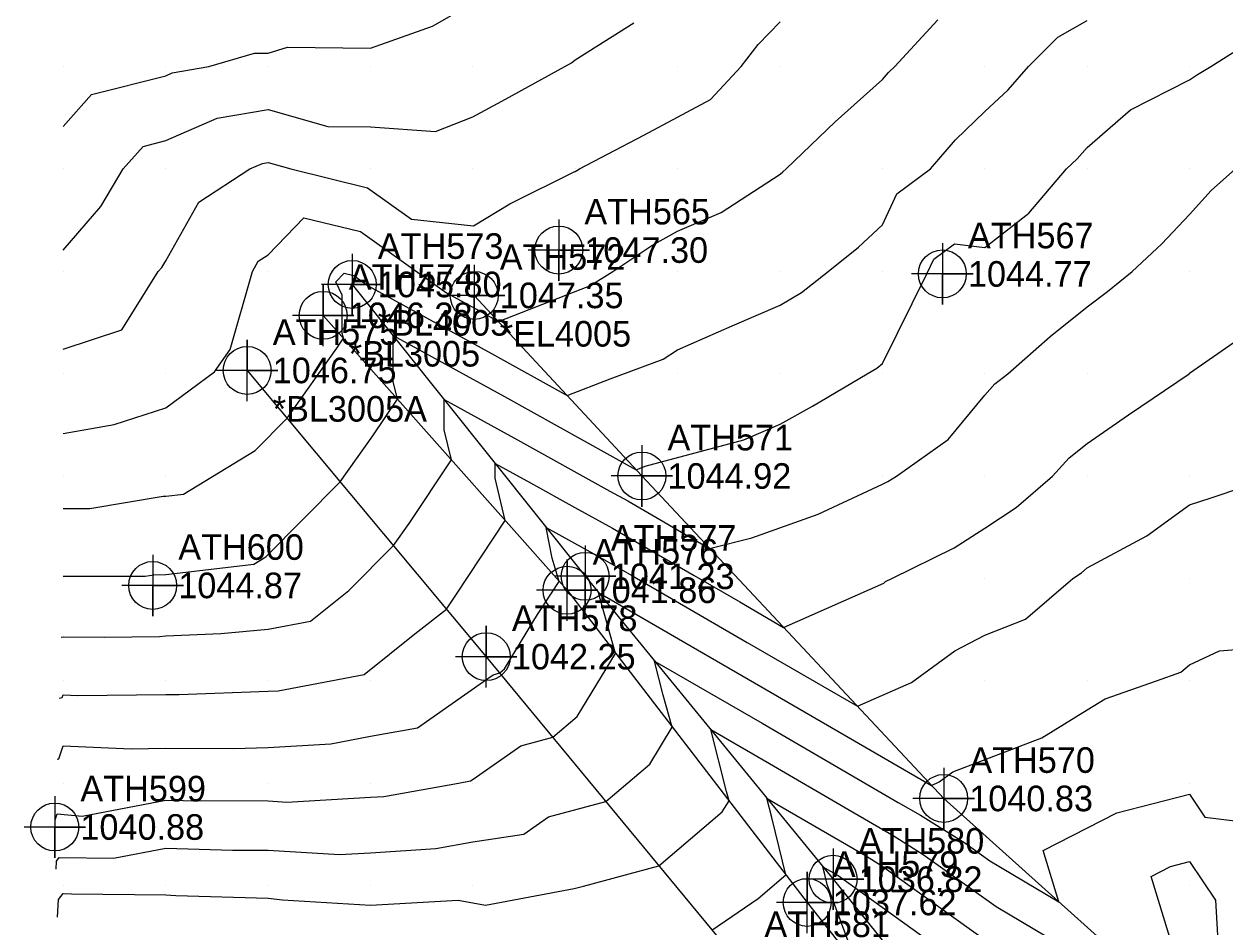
# Model space of a CAD drawing. Extents: x 1213164 to 1213550, y 766120 to 766870.
# Drawn here: x 1213226.2 to 1213343.5, y 766656 to 766744.2 of the extents above; entities that cross this region are included whole.
import ezdxf

# ---------------------------------------------------------------- set-up
doc = ezdxf.new("R2010")
doc.units = 0
for name, color, linetype in [('Default', 7, 'Continuous'), ('Exist DTM Breakline', 7, 'Continuous'), ('Exist DTM Breakline Cogo Comment', 7, 'Continuous'), ('Exist DTM Breakline Cogo Elevation', 7, 'Continuous'), ('Exist DTM Breakline Cogo Number', 7, 'Continuous'), ('Exist DTM Breakline Cogo Point CELL', 7, 'Continuous'), ('Exist DTM QL2 LIDAR Elevation Point', 7, 'Continuous'), ('Exist DTM Regular Point CELL', 7, 'Continuous'), ('Exist DTM Regular Point Cogo Elevation', 7, 'Continuous'), ('Exist DTM Regular Point Cogo Number', 7, 'Continuous'), ('Exist Roads Soil', 7, 'Continuous'), ('Exist Roads Soil Cogo Comment', 7, 'Continuous'), ('Exist Roads Soil Cogo Elevation', 7, 'Continuous'), ('Exist Roads Soil Cogo Number', 7, 'Continuous'), ('Exist Roads Soil Cogo Point CELL', 7, 'Continuous')]:
    doc.layers.add(name, color=color, linetype=linetype)

msp = doc.modelspace()

# ---------------------------------------------------------------- linework, layer by layer
at = {"layer": 'Default'}
for points in [[(1213230, 766734.16), (1213232.74, 766737.26), (1213240, 766739.11), (1213240.62, 766739.38), (1213244.2, 766740), (1213248.69, 766741.31), (1213250, 766741.32), (1213251.89, 766741.89), (1213260, 766741.81), (1213266.05, 766743.95), (1213270, 766746.2)], [(1213230, 766704.16), (1213234.96, 766705.04), (1213240, 766706.68), (1213244.77, 766710.19), (1213246.29, 766712.35), (1213248.47, 766720), (1213249.02, 766720.98), (1213250, 766721.61), (1213253.48, 766725.23), (1213259.04, 766723.88), (1213267.43, 766717.89), (1213270.57, 766716.17), (1213272.49, 766715.1), (1213280.57, 766718.25), (1213281.43, 766718.57), (1213283.67, 766720), (1213287.48, 766722.52), (1213290, 766723.93), (1213294.26, 766725.74), (1213300, 766729.49), (1213300.28, 766729.72), (1213300.59, 766730), (1213305.38, 766734.62), (1213310, 766738.73), (1213310.59, 766739.41), (1213311.2, 766740), (1213315.42, 766744.58)], [(1213230, 766696.84), (1213232.59, 766696.84), (1213239.77, 766698.04), (1213240, 766698.04), (1213241.75, 766698.25), (1213248.75, 766702.51), (1213251.86, 766705.65), (1213256.71, 766712.49), (1213257.36, 766713.47), (1213257.25, 766713.93), (1213257.23, 766717.67), (1213256.62, 766718.97), (1213257.43, 766719.81), (1213258.36, 766719.58), (1213259.76, 766718.58), (1213271.83, 766711.96), (1213279.22, 766707.86), (1213283.42, 766709.5), (1213288.57, 766711.43), (1213290, 766712.34), (1213295.33, 766714.67), (1213300, 766716.71), (1213302.08, 766717.92), (1213304.69, 766720), (1213307.65, 766722.35), (1213310, 766724.55), (1213311.39, 766727.56), (1213314.7, 766730), (1213317.15, 766732.85), (1213320, 766735.62), (1213322.28, 766737.72), (1213324.26, 766740), (1213327.13, 766742.87), (1213330, 766744.49)], [(1213230, 766712.41), (1213235.71, 766714.29), (1213239.28, 766720), (1213239.61, 766720.39), (1213240, 766721.04), (1213243.25, 766726.75), (1213248.23, 766730), (1213249.47, 766730.53), (1213250, 766730.63), (1213252.21, 766730), (1213259.71, 766728.17), (1213264.01, 766725.1), (1213270.06, 766724.44), (1213273.6, 766726.6), (1213279.95, 766729.77), (1213280, 766729.74), (1213280.16, 766729.84), (1213280.43, 766730), (1213286.7, 766733.3), (1213290, 766735.05), (1213293.22, 766736.78), (1213296.19, 766740), (1213297.85, 766742.15), (1213300, 766744.39)], [(1213230, 766722.08), (1213233.66, 766726.34), (1213235.85, 766730), (1213237.79, 766732.21), (1213240, 766732.77), (1213245.04, 766734.96), (1213250, 766735.82), (1213255.84, 766734.16), (1213260, 766734.13), (1213266.34, 766733.66), (1213270, 766735.08), (1213273.18, 766736.82), (1213278.97, 766740), (1213279.62, 766740.38), (1213280, 766740.67), (1213285.73, 766744.27)], [(1213230, 766690.24), (1213238, 766690.21), (1213238.85, 766690.36), (1213240, 766690.38), (1213248.61, 766691.39), (1213249.79, 766692.11), (1213257.05, 766699.43), (1213260.24, 766703.94), (1213262.63, 766707.53), (1213262.23, 766709.23), (1213262.21, 766713.73), (1213273.1, 766707.76), (1213285.95, 766700.62), (1213286.27, 766700.74), (1213286.84, 766700.96), (1213296.46, 766703.54), (1213300, 766705.08), (1213303.16, 766706.84), (1213308.5, 766710), (1213309.45, 766710.55), (1213310, 766710.99), (1213314.37, 766719.81), (1213315.02, 766721.2), (1213317.04, 766722.7), (1213320, 766722.32), (1213324.3, 766725.7), (1213327.96, 766730), (1213329.02, 766730.98), (1213330, 766732.1), (1213334.22, 766735.78), (1213340, 766738.7), (1213340.78, 766739.22), (1213342.06, 766740), (1213346.92, 766743.08)], [(1213229.8, 766684.27), (1213230, 766684.3), (1213233.98, 766684.26), (1213239.41, 766684.33), (1213240, 766684.41), (1213245.39, 766684.61), (1213250, 766685.05), (1213254.16, 766685.84), (1213257.88, 766688.83), (1213262.24, 766693.22), (1213263.78, 766695.38), (1213267.9, 766701.59), (1213267.21, 766704.52), (1213267.19, 766707.48), (1213274.36, 766703.55), (1213283.38, 766698.54), (1213285.13, 766697.57), (1213293.12, 766692.94), (1213297.24, 766693.96), (1213303.71, 766696.29), (1213310, 766699.2), (1213310.54, 766699.46), (1213311.37, 766700), (1213316.41, 766703.59), (1213320, 766707.91), (1213320.99, 766709.01), (1213322.26, 766710), (1213326.38, 766713.62), (1213330, 766716.55), (1213331.98, 766718.02), (1213334.4, 766720), (1213337.3, 766722.7), (1213340, 766725.54), (1213342.11, 766727.89), (1213344.49, 766730)], [(1213229.6, 766678.31), (1213229.9, 766678.37), (1213230, 766678.63), (1213231.42, 766678.58), (1213240, 766678.68), (1213241.33, 766678.67), (1213250, 766678.98), (1213250.97, 766679.03), (1213256.12, 766680), (1213259.38, 766680.62), (1213264.32, 766684.58), (1213267.43, 766687), (1213268.39, 766688.46), (1213273.16, 766695.65), (1213272.18, 766699.81), (1213272.17, 766701.24), (1213275.62, 766699.35), (1213279.96, 766696.94), (1213283.63, 766694.91), (1213291.6, 766690.29), (1213296.06, 766687.71), (1213300.34, 766685.22), (1213310.12, 766689.55), (1213310.31, 766689.69), (1213310.91, 766690), (1213317.01, 766692.99), (1213320, 766694.9), (1213323.07, 766696.93), (1213326.62, 766700), (1213328.22, 766701.78), (1213330, 766703.17), (1213334.02, 766705.98), (1213339.95, 766710), (1213339.98, 766710.02), (1213340, 766710.04), (1213345.86, 766714.14)], [(1213229.39, 766672.36), (1213229.56, 766672.39), (1213230, 766673.64), (1213236.63, 766673.37), (1213240, 766673.41), (1213246.61, 766673.39), (1213250, 766673.5), (1213256.14, 766673.86), (1213260, 766674.59), (1213264.58, 766675.42), (1213271.05, 766679.95), (1213271.99, 766680.6), (1213272.62, 766680.77), (1213273.1, 766681.18), (1213276.32, 766686.48), (1213278.43, 766689.71), (1213277.76, 766691.98), (1213277.16, 766694.99), (1213282.12, 766692.25), (1213285.58, 766690.25), (1213296.78, 766683.76), (1213307.56, 766677.51), (1213312.83, 766679.84), (1213317.06, 766682.94), (1213320, 766684.47), (1213323.96, 766686.04), (1213328.6, 766690), (1213329.44, 766690.56), (1213330, 766691.04), (1213335.82, 766694.18), (1213340, 766697.18), (1213342.11, 766697.89), (1213348.38, 766700)], [(1213229.19, 766666.41), (1213229.21, 766666.42), (1213229.41, 766667), (1213231.85, 766666.78), (1213240, 766668.35), (1213241.7, 766668.3), (1213250, 766668.27), (1213251.84, 766668.16), (1213260, 766668.63), (1213261.29, 766668.71), (1213268.59, 766670), (1213269.78, 766670.22), (1213270.04, 766670.4), (1213274.69, 766673.66), (1213277.8, 766674.49), (1213280.19, 766676.52), (1213283.93, 766682.68), (1213282.42, 766688), (1213282.26, 766688.64), (1213297.51, 766679.81), (1213314.78, 766669.79), (1213315.53, 766670.12), (1213316.89, 766671.12), (1213325.56, 766674.44), (1213330, 766677.18), (1213331.75, 766678.25), (1213336.75, 766680), (1213339.15, 766680.85), (1213340, 766681.57), (1213342.93, 766682.93), (1213350.15, 766683.51)], [(1213229.3, 766661.59), (1213229.34, 766662.4), (1213229.6, 766662.73), (1213234.92, 766662.68), (1213240, 766663.66), (1213246.54, 766663.46), (1213250, 766663.45), (1213256.96, 766663.04), (1213260, 766663.21), (1213266.38, 766663.62), (1213270, 766664.26), (1213274.98, 766665.02), (1213277.39, 766666.71), (1213282.98, 766668.21), (1213287.28, 766671.85), (1213289.48, 766675.48), (1213288.59, 766678.6), (1213287.74, 766681.93), (1213298.24, 766675.86), (1213311.55, 766668.13), (1213313.73, 766666.87), (1213318.04, 766664.17), (1213320.48, 766662.41), (1213327.23, 766658.41), (1213325.69, 766663.43), (1213332.89, 766667.11), (1213340, 766668.93), (1213341.5, 766666.67), (1213348.94, 766665.78)], [(1213229.45, 766656.92), (1213229.54, 766658.65), (1213230, 766659.24), (1213230.8, 766659.2), (1213240, 766659.09), (1213240.98, 766659.02), (1213250, 766658.77), (1213251.4, 766658.6), (1213260, 766658.1), (1213268.57, 766658.57), (1213271.22, 766658.1), (1213279.9, 766659.73), (1213280.8, 766659.95), (1213288.17, 766661.93), (1213294.36, 766667.19), (1213295.02, 766668.27), (1213294.76, 766669.2), (1213293.23, 766675.23), (1213298.96, 766671.91), (1213306.24, 766667.69), (1213311.04, 766664.9), (1213313.99, 766663.05), (1213321.09, 766657.94), (1213340.71, 766646.3), (1213336.25, 766660.9), (1213338.14, 766661.86), (1213340, 766662.34), (1213342.51, 766658.57), (1213343.19, 766647.14)], [(1213293.35, 766655.64), (1213297.85, 766658.75), (1213300.56, 766661.06), (1213299.93, 766663.71), (1213299.19, 766666.64), (1213298.71, 766668.53), (1213299.69, 766667.96), (1213300.93, 766667.24), (1213308.35, 766662.94), (1213309.95, 766661.94), (1213321.7, 766653.48)], [(1213306.74, 766654.3), (1213304.61, 766660.11), (1213304.38, 766661.09), (1213304.19, 766661.82), (1213305.66, 766660.97), (1213305.9, 766660.82), (1213322.31, 766649.01)]]:
    msp.add_lwpolyline(points, dxfattribs=at)
at = {"layer": 'Exist DTM Breakline'}
for points in [[(1213393.73, 766837.71), (1213387.94, 766804.2), (1213372.97, 766750.1), (1213364.41, 766714.77), (1213354.91, 766685.16), (1213342.45, 766644.74), (1213315.98, 766668.51), (1213286.51, 766700.01), (1213270.13, 766717.65)], [(1213258.22, 766718.72), (1213280.97, 766690.21), (1213305.18, 766660.62), (1213332.72, 766626.34), (1213338.93, 766619.05), (1213344.38, 766617.29)]]:
    msp.add_lwpolyline(points, dxfattribs=at)
at = {"layer": 'Exist DTM Breakline Cogo Point CELL'}
for points in [[(1213258.22, 766721.72), (1213258.22, 766715.72), (1213258.22, 766718.72), (1213261.22, 766718.72), (1213255.22, 766718.72)], [(1213270.13, 766720.65), (1213270.13, 766714.65), (1213270.13, 766717.65), (1213273.13, 766717.65), (1213267.13, 766717.65)], [(1213286.51, 766703.01), (1213286.51, 766697.01), (1213286.51, 766700.01), (1213289.51, 766700.01), (1213283.51, 766700.01)], [(1213280.97, 766693.21), (1213280.97, 766687.21), (1213280.97, 766690.21), (1213283.97, 766690.21), (1213277.97, 766690.21)], [(1213315.98, 766671.51), (1213315.98, 766665.51), (1213315.98, 766668.51), (1213318.98, 766668.51), (1213312.98, 766668.51)], [(1213305.18, 766663.62), (1213305.18, 766657.62), (1213305.18, 766660.62), (1213308.18, 766660.62), (1213302.18, 766660.62)]]:
    msp.add_lwpolyline(points, dxfattribs=at)
for centre in [(1213258.22, 766718.72), (1213270.13, 766717.65), (1213286.51, 766700.01), (1213280.97, 766690.21), (1213315.98, 766668.51), (1213305.18, 766660.62)]:
    msp.add_circle(centre, 2.34, dxfattribs=at)
at = {"layer": 'Exist DTM QL2 LIDAR Elevation Point'}
for p, q in [((1213230, 766740), (1213230, 766740)), ((1213240, 766740), (1213240, 766740)), ((1213250, 766740), (1213250, 766740)), ((1213260, 766740), (1213260, 766740)), ((1213270, 766740), (1213270, 766740)), ((1213280, 766740), (1213280, 766740)), ((1213290, 766740), (1213290, 766740)), ((1213300, 766740), (1213300, 766740)), ((1213310, 766740), (1213310, 766740)), ((1213320, 766740), (1213320, 766740)), ((1213330, 766740), (1213330, 766740)), ((1213340, 766740), (1213340, 766740)), ((1213230, 766730), (1213230, 766730)), ((1213240, 766730), (1213240, 766730)), ((1213250, 766730), (1213250, 766730)), ((1213260, 766730), (1213260, 766730)), ((1213270, 766730), (1213270, 766730)), ((1213280, 766730), (1213280, 766730)), ((1213290, 766730), (1213290, 766730)), ((1213300, 766730), (1213300, 766730)), ((1213310, 766730), (1213310, 766730)), ((1213320, 766730), (1213320, 766730)), ((1213330, 766730), (1213330, 766730)), ((1213340, 766730), (1213340, 766730)), ((1213230, 766720), (1213230, 766720)), ((1213240, 766720), (1213240, 766720)), ((1213250, 766720), (1213250, 766720)), ((1213280, 766720), (1213280, 766720)), ((1213290, 766720), (1213290, 766720)), ((1213300, 766720), (1213300, 766720)), ((1213310, 766720), (1213310, 766720)), ((1213320, 766720), (1213320, 766720)), ((1213330, 766720), (1213330, 766720)), ((1213340, 766720), (1213340, 766720)), ((1213230, 766710), (1213230, 766710)), ((1213240, 766710), (1213240, 766710)), ((1213290, 766710), (1213290, 766710)), ((1213300, 766710), (1213300, 766710)), ((1213310, 766710), (1213310, 766710)), ((1213320, 766710), (1213320, 766710)), ((1213330, 766710), (1213330, 766710)), ((1213340, 766710), (1213340, 766710)), ((1213230, 766700), (1213230, 766700)), ((1213240, 766700), (1213240, 766700)), ((1213300, 766700), (1213300, 766700)), ((1213310, 766700), (1213310, 766700)), ((1213320, 766700), (1213320, 766700)), ((1213330, 766700), (1213330, 766700)), ((1213340, 766700), (1213340, 766700)), ((1213230, 766690), (1213230, 766690)), ((1213240, 766690), (1213240, 766690)), ((1213250, 766690), (1213250, 766690)), ((1213310, 766690), (1213310, 766690)), ((1213320, 766690), (1213320, 766690)), ((1213330, 766690), (1213330, 766690)), ((1213340, 766690), (1213340, 766690)), ((1213230, 766680), (1213230, 766680)), ((1213240, 766680), (1213240, 766680)), ((1213250, 766680), (1213250, 766680)), ((1213260, 766680), (1213260, 766680)), ((1213320, 766680), (1213320, 766680)), ((1213330, 766680), (1213330, 766680)), ((1213340, 766680), (1213340, 766680)), ((1213230, 766670), (1213230, 766670)), ((1213240, 766670), (1213240, 766670)), ((1213250, 766670), (1213250, 766670)), ((1213260, 766670), (1213260, 766670)), ((1213270, 766670), (1213270, 766670)), ((1213330, 766670), (1213330, 766670)), ((1213340, 766670), (1213340, 766670)), ((1213230, 766660), (1213230, 766660)), ((1213240, 766660), (1213240, 766660)), ((1213250, 766660), (1213250, 766660)), ((1213260, 766660), (1213260, 766660)), ((1213270, 766660), (1213270, 766660)), ((1213280, 766660), (1213280, 766660)), ((1213340, 766660), (1213340, 766660))]:
    msp.add_line(p, q, dxfattribs=at)
at = {"layer": 'Exist DTM Regular Point CELL'}
for points in [[(1213278.39, 766725.08), (1213278.39, 766719.08), (1213278.39, 766722.08), (1213281.39, 766722.08), (1213275.39, 766722.08)], [(1213315.85, 766722.75), (1213315.85, 766716.75), (1213315.85, 766719.75), (1213318.85, 766719.75), (1213312.85, 766719.75)], [(1213238.73, 766692.32), (1213238.73, 766686.32), (1213238.73, 766689.32), (1213241.73, 766689.32), (1213235.73, 766689.32)], [(1213229.17, 766668.72), (1213229.17, 766662.72), (1213229.17, 766665.72), (1213232.17, 766665.72), (1213226.17, 766665.72)]]:
    msp.add_lwpolyline(points, dxfattribs=at)
for centre in [(1213278.39, 766722.08), (1213315.85, 766719.75), (1213238.73, 766689.32), (1213229.17, 766665.72)]:
    msp.add_circle(centre, 2.34, dxfattribs=at)
at = {"layer": 'Exist Roads Soil'}
for points in [[(1213255.38, 766715.7), (1213279.2, 766688.85), (1213302.65, 766658.35), (1213330, 766623.78), (1213351.29, 766609.62)], [(1213247.96, 766710.32), (1213271.31, 766682.36), (1213295.97, 766652.47)]]:
    msp.add_lwpolyline(points, dxfattribs=at)
at = {"layer": 'Exist Roads Soil Cogo Point CELL'}
for points in [[(1213255.38, 766712.7), (1213255.38, 766718.7), (1213255.38, 766715.7), (1213258.38, 766715.7), (1213252.38, 766715.7)], [(1213247.96, 766707.32), (1213247.96, 766713.32), (1213247.96, 766710.32), (1213250.96, 766710.32), (1213244.96, 766710.32)], [(1213279.2, 766685.85), (1213279.2, 766691.85), (1213279.2, 766688.85), (1213282.2, 766688.85), (1213276.2, 766688.85)], [(1213271.31, 766679.36), (1213271.31, 766685.36), (1213271.31, 766682.36), (1213274.31, 766682.36), (1213268.31, 766682.36)], [(1213302.65, 766655.35), (1213302.65, 766661.35), (1213302.65, 766658.35), (1213305.65, 766658.35), (1213299.65, 766658.35)]]:
    msp.add_lwpolyline(points, dxfattribs=at)
for centre in [(1213255.38, 766715.7), (1213247.96, 766710.32), (1213279.2, 766688.85), (1213271.31, 766682.36), (1213302.65, 766658.35)]:
    msp.add_circle(centre, 2.34, dxfattribs=at)

# ---------------------------------------------------------------- texts
at = {"layer": 'Exist DTM Breakline Cogo Comment'}
for s, p in [('*BL4005', (1213260.72, 766713.72)), ('*EL4005', (1213272.63, 766712.65))]:
    msp.add_text(s, height=2.5, dxfattribs=at).set_placement(p)
at = {"layer": 'Exist DTM Breakline Cogo Elevation'}
for s, p in [('1045.80', (1213260.72, 766717.47)), ('1047.35', (1213272.63, 766716.4)), ('1044.92', (1213289.01, 766698.76)), ('1041.23', (1213283.47, 766688.96)), ('1040.83', (1213318.48, 766667.26)), ('1036.82', (1213307.68, 766659.37))]:
    msp.add_text(s, height=2.5, dxfattribs=at).set_placement(p)
at = {"layer": 'Exist DTM Breakline Cogo Number'}
for s, p in [('ATH573', (1213260.72, 766721.22)), ('ATH572', (1213272.63, 766720.15)), ('ATH571', (1213289.01, 766702.51)), ('ATH577', (1213283.47, 766692.71)), ('ATH570', (1213318.48, 766671.01)), ('ATH580', (1213307.68, 766663.12))]:
    msp.add_text(s, height=2.5, dxfattribs=at).set_placement(p)
at = {"layer": 'Exist DTM Regular Point Cogo Elevation'}
for s, p in [('1047.30', (1213280.89, 766720.83)), ('1044.77', (1213318.35, 766718.5)), ('1044.87', (1213241.23, 766688.07)), ('1040.88', (1213231.67, 766664.47))]:
    msp.add_text(s, height=2.5, dxfattribs=at).set_placement(p)
at = {"layer": 'Exist DTM Regular Point Cogo Number'}
for s, p in [('ATH565', (1213280.89, 766724.58)), ('ATH567', (1213318.35, 766722.25)), ('ATH600', (1213241.23, 766691.82)), ('ATH599', (1213231.67, 766668.22))]:
    msp.add_text(s, height=2.5, dxfattribs=at).set_placement(p)
at = {"layer": 'Exist Roads Soil Cogo Comment'}
for s, p in [('*BL3005', (1213257.88, 766710.7)), ('*BL3005A', (1213250.46, 766705.32))]:
    msp.add_text(s, height=2.5, dxfattribs=at).set_placement(p)
at = {"layer": 'Exist Roads Soil Cogo Elevation'}
for s, p in [('1046.38', (1213257.88, 766714.45)), ('1046.75', (1213250.46, 766709.07)), ('1041.86', (1213281.7, 766687.6)), ('1042.25', (1213273.81, 766681.11)), ('1037.62', (1213305.15, 766657.1))]:
    msp.add_text(s, height=2.5, dxfattribs=at).set_placement(p)
at = {"layer": 'Exist Roads Soil Cogo Number'}
for s, p in [('ATH574', (1213257.88, 766718.2)), ('ATH575', (1213250.46, 766712.82)), ('ATH576', (1213281.7, 766691.35)), ('ATH578', (1213273.81, 766684.86)), ('ATH579', (1213305.15, 766660.85)), ('ATH581', (1213298.47, 766654.97))]:
    msp.add_text(s, height=2.5, dxfattribs=at).set_placement(p)

doc.saveas('drawing.dxf')
